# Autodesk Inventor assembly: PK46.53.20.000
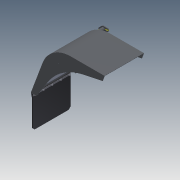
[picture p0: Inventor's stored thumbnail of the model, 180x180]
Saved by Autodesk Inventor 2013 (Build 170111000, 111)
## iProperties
Created: 2005-03
Part Number: PK46.53.20.000
Document SubType Name: Assembly
Designer: HKostja
Manufacturer: Standard
Standards Organization: Custom
Description: front
Author: HKostja
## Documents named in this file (17)
- D:\FrontLoaderVault\Data\Assy, Chassis, Front\PK46.53.20.000.iam
- D:\FrontLoaderVault\Data\Assy, Chassis, Front\PK46.53.20.001.ipt
- D:\FrontLoaderVault\Data\Assy, Chassis, Front\PK46.53.20.001-01.ipt
- D:\FrontLoaderVault\Data\Assy, Chassis, Front\PK46.53.20.002.ipt
- D:\FrontLoaderVault\Data\Assy, Chassis, Front\PK46.53.20.004.ipt
- D:\FrontLoaderVault\Data\Assy, Chassis, Front\PK46.53.20.003.ipt
- D:\FrontLoaderVault\Data\Assy, Chassis, Front\PK46.53.20.005.ipt
- D:\FrontLoaderVault\Data\Assy, Chassis, Front\PK46.53.20.006.ipt
- D:\FrontLoaderVault\Data\Assy, Chassis, Front\M10-6H.5.019(S16).ipt
- D:\FrontLoaderVault\Data\Assy, Chassis, Front\10.65G.019.ipt
- D:\FrontLoaderVault\Data\Assy, Chassis, Front\M10-6gx30.58.019(S16).ipt
- D:\FrontLoaderVault\Data\Assy, Chassis, Front\PK46.53.20.007.ipt
- PK46.53.20.004.ipt
- PK46.53.20.005.ipt
- M10-6H.5.019(S16).ipt
- 10.65G.019.ipt
- M10-6gx30.58.019(S16).ipt
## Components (26 placed, 11 different names)
1. PK46.53.20.001:1 — Flush:2, Mate:9, Mate:10, Mate:8, Mate:14, Mate:15
2. PK46.53.20.001-01:1 — Mate:7, Flush:3, Mate:13, Mate:16, Mate:17, Mate:22, Mate:26
3. PK46.53.20.002:1 — Mate:7, Flush:2, Mate:9, Flush:3, Mate:10, Mate:8, Mate:13, Angle:1, Angle:2, Insert:3, Mate:20, Insert:20, Insert:21, Insert:22, Insert:23, Insert:24, Mate:28, Mate:29
4. PK46.53.20.003:1 — Mate:14, Mate:16, Insert:2, Mate:18, Tangent:1, Tangent:2
5. PK46.53.20.003:2 — Mate:15, Mate:17, Insert:1, Mate:19, Angle:1, Mate:23, Mate:25
6. PK46.53.20.007:3 — Insert:2, Mate:18, Angle:2
7. PK46.53.20.007:2 — Insert:1, Mate:19
8. PK46.53.20.004:1 — Mate:21, Insert:4, Insert:10, Insert:11, Insert:12, Insert:13, Insert:14
9. PK46.53.20.005:1 — Insert:3, Mate:20, Mate:21, Insert:4
10. M10-6gx30.58.019(S16):5 — Insert:24, Flush:4
11. M10-6gx30.58.019(S16):4 — Insert:23, Flush:4, Flush:5
12. M10-6gx30.58.019(S16):3 — Insert:22, Flush:5, Flush:6
13. M10-6gx30.58.019(S16):2 — Insert:21, Flush:6, Flush:7
14. M10-6gx30.58.019(S16):1 — Insert:20, Flush:7
15. M10-6H.5.019(S16):1 — Insert:16, Flush:8, Flush:9
16. M10-6H.5.019(S16):2 — Insert:17, Flush:9, Flush:10
17. M10-6H.5.019(S16):3 — Insert:18, Flush:10, Flush:11
18. M10-6H.5.019(S16):4 — Insert:19, Flush:11
19. M10-6H.5.019(S16):5 — Insert:15, Flush:8
20. 10.65G.019:1 — Insert:10, Insert:19
21. 10.65G.019:2 — Insert:11, Insert:18
22. 10.65G.019:3 — Insert:12, Insert:17
23. 10.65G.019:4 — Insert:13, Insert:15
24. 10.65G.019:5 — Insert:14, Insert:16
25. PK46.53.20.006:1 — Mate:22, Mate:23, Mate:25, Tangent:2
26. PK46.53.20.006:2 — Mate:26, Mate:28, Tangent:1, Mate:29
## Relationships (52: Mate 19, Insert 19, Flush 10, Angle 2, Tangent 2)
- Mate:7: PK46.53.20.001-01:1 ↔ PK46.53.20.002:1
- Flush:2: PK46.53.20.001:1 ↔ PK46.53.20.002:1
- Mate:9: PK46.53.20.001:1 ↔ PK46.53.20.002:1
- Flush:3: PK46.53.20.001-01:1 ↔ PK46.53.20.002:1
- Mate:10: PK46.53.20.001:1 ↔ PK46.53.20.002:1
- Mate:8: PK46.53.20.001:1 ↔ PK46.53.20.002:1
- Mate:13: PK46.53.20.001-01:1 ↔ PK46.53.20.002:1
- Mate:14: PK46.53.20.001:1 ↔ PK46.53.20.003:1
- Mate:15: PK46.53.20.001:1 ↔ PK46.53.20.003:2
- Mate:16: PK46.53.20.001-01:1 ↔ PK46.53.20.003:1
- Mate:17: PK46.53.20.001-01:1 ↔ PK46.53.20.003:2
- Insert:1: PK46.53.20.003:2 ↔ PK46.53.20.007:2
- Insert:2: PK46.53.20.003:1 ↔ PK46.53.20.007:3
- Mate:18: PK46.53.20.003:1 ↔ PK46.53.20.007:3
- Mate:19: PK46.53.20.003:2 ↔ PK46.53.20.007:2
- Angle:1: PK46.53.20.002:1 ↔ PK46.53.20.003:2
- Angle:2: PK46.53.20.002:1 ↔ PK46.53.20.007:3
- Insert:3: PK46.53.20.002:1 ↔ PK46.53.20.005:1
- Mate:20: PK46.53.20.002:1 ↔ PK46.53.20.005:1
- Mate:21: PK46.53.20.004:1 ↔ PK46.53.20.005:1
- Insert:4: PK46.53.20.004:1 ↔ PK46.53.20.005:1
- Insert:10: PK46.53.20.004:1 ↔ 10.65G.019:1
- Insert:11: PK46.53.20.004:1 ↔ 10.65G.019:2
- Insert:12: PK46.53.20.004:1 ↔ 10.65G.019:3
- Insert:13: PK46.53.20.004:1 ↔ 10.65G.019:4
- Insert:14: PK46.53.20.004:1 ↔ 10.65G.019:5
- Insert:15: M10-6H.5.019(S16):5 ↔ 10.65G.019:4
- Insert:16: M10-6H.5.019(S16):1 ↔ 10.65G.019:5
- Insert:17: M10-6H.5.019(S16):2 ↔ 10.65G.019:3
- Insert:18: M10-6H.5.019(S16):3 ↔ 10.65G.019:2
- Insert:19: M10-6H.5.019(S16):4 ↔ 10.65G.019:1
- Insert:20: PK46.53.20.002:1 ↔ M10-6gx30.58.019(S16):1
- Insert:21: PK46.53.20.002:1 ↔ M10-6gx30.58.019(S16):2
- Insert:22: PK46.53.20.002:1 ↔ M10-6gx30.58.019(S16):3
- Insert:23: PK46.53.20.002:1 ↔ M10-6gx30.58.019(S16):4
- Insert:24: PK46.53.20.002:1 ↔ M10-6gx30.58.019(S16):5
- Flush:4: M10-6gx30.58.019(S16):5 ↔ M10-6gx30.58.019(S16):4
- Flush:5: M10-6gx30.58.019(S16):4 ↔ M10-6gx30.58.019(S16):3
- Flush:6: M10-6gx30.58.019(S16):3 ↔ M10-6gx30.58.019(S16):2
- Flush:7: M10-6gx30.58.019(S16):2 ↔ M10-6gx30.58.019(S16):1
- Flush:8: M10-6H.5.019(S16):1 ↔ M10-6H.5.019(S16):5
- Flush:9: M10-6H.5.019(S16):1 ↔ M10-6H.5.019(S16):2
- Flush:10: M10-6H.5.019(S16):2 ↔ M10-6H.5.019(S16):3
- Flush:11: M10-6H.5.019(S16):3 ↔ M10-6H.5.019(S16):4
- Mate:22: PK46.53.20.001-01:1 ↔ PK46.53.20.006:1
- Mate:23: PK46.53.20.003:2 ↔ PK46.53.20.006:1
- Mate:25: PK46.53.20.003:2 ↔ PK46.53.20.006:1
- Mate:26: PK46.53.20.001-01:1 ↔ PK46.53.20.006:2
- Mate:28: PK46.53.20.002:1 ↔ PK46.53.20.006:2
- Tangent:1: PK46.53.20.003:1 ↔ PK46.53.20.006:2
- Mate:29: PK46.53.20.002:1 ↔ PK46.53.20.006:2
- Tangent:2: PK46.53.20.003:1 ↔ PK46.53.20.006:1
